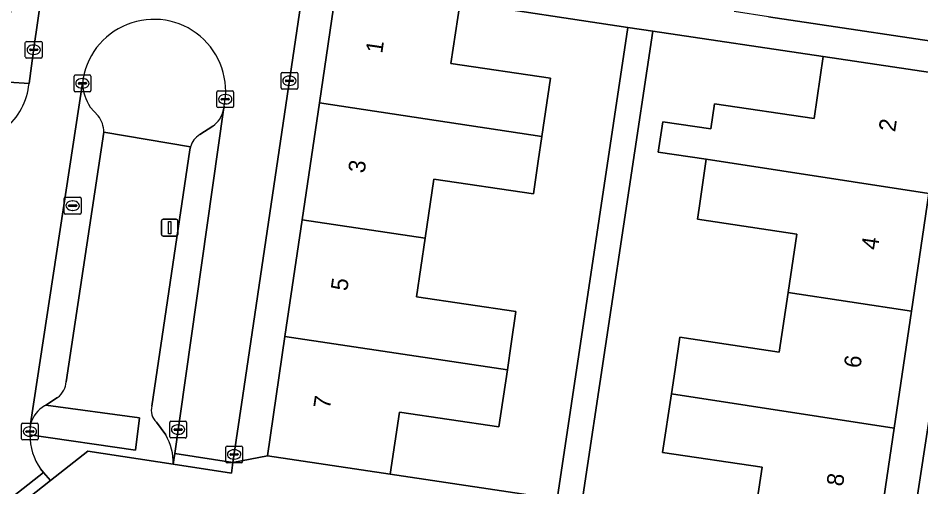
# Model space of a CAD drawing. Extents: x 163683 to 164494, y 382709 to 383872.
# Drawn here: x 163986.6 to 164040.4, y 383061.8 to 383089.7 of the extents above; entities that cross this region are included whole.
import ezdxf

# ---------------------------------------------------------------- set-up
doc = ezdxf.new("R2010")
doc.units = 0
for name, color, linetype in [('IMGEO_Erf', 7, 'Continuous'), ('IMGEO_Groenvoorziening', 7, 'Continuous'), ('IMGEO_Kolk', 7, 'Continuous'), ('IMGEO_Lichtmast', 7, 'Continuous'), ('IMGEO_Pand', 7, 'Continuous'), ('IMGEO_Pand_nummerreeks', 7, 'Continuous'), ('IMGEO_Parkeervlak_open', 7, 'Continuous'), ('IMGEO_Rijbaan_lokaal_open', 7, 'Continuous'), ('IMGEO_Rioolput', 7, 'Continuous'), ('IMGEO_Voetpad_open', 7, 'Continuous')]:
    doc.layers.add(name, color=color, linetype=linetype)

msp = doc.modelspace()

# ---------------------------------------------------------------- linework, layer by layer
at = {"layer": 'IMGEO_Erf'}
for points in [[(164022.964, 383089.182), (164012.951, 383090.682), (164012.41, 383087.025), (164018.347, 383086.148), (164017.834, 383082.676), (164017.616, 383081.202), (164017.328, 383079.253), (164011.392, 383080.13), (164010.87, 383076.601), (164010.353, 383073.107), (164016.29, 383072.23), (164016.005, 383070.301), (164015.775, 383068.743), (164015.274, 383065.354), (164009.338, 383066.231), (164008.789, 383062.521), (164018.747, 383061.027)], [(164033.045, 383076.853), (164027.111, 383077.737), (164027.209, 383078.398), (164027.643, 383081.312), (164024.777, 383081.738), (164025.045, 383083.549), (164027.913, 383083.122), (164028.136, 383084.621), (164034.07, 383083.737), (164034.621, 383087.436), (164024.449, 383088.96), (164020.223, 383060.805), (164030.426, 383059.273), (164030.971, 383062.937), (164025.038, 383063.821), (164025.558, 383067.31), (164025.775, 383068.767), (164026.062, 383070.695), (164031.996, 383069.811), (164032.527, 383073.373)]]:
    msp.add_lwpolyline(points, close=True, dxfattribs=at)
at = {"layer": 'IMGEO_Groenvoorziening'}
for points in [[(164031.356, 383089.811), (164044.132, 383087.893), (164043.843, 383085.984), (164043.851, 383085.289)], [(163990.898, 383084.429), (163991.368, 383083.909)], [(163998.849, 383084.264), (163998.879, 383084.473)], [(163996.842, 383081.879), (163996.877, 383082.051), (163991.711, 383082.931), (163989.459, 383068.037)], [(163991.711, 383082.931), (163996.877, 383082.051)], [(163997.425, 383082.781), (163998.2, 383083.289)], [(163994.577, 383066.591), (163996.842, 383081.879)], [(163988.951, 383067.097), (163988.239, 383066.641), (163993.84, 383065.897), (163993.591, 383063.961), (163987.293, 383064.864)], [(163987.293, 383064.864), (163993.591, 383063.961), (163993.84, 383065.897), (163988.239, 383066.641)], [(163988.239, 383066.641), (163988.177, 383066.601)], [(163987.342, 383065.521), (163987.311, 383065.284)], [(163995.403, 383064.865), (163994.844, 383065.639)], [(163987.926, 383062.844), (163988.107, 383062.634), (163988.526, 383062.149), (163990.75, 383063.896), (163995.848, 383063.119)]]:
    msp.add_lwpolyline(points, dxfattribs=at)
for centre, radius, start, end in [((163994.69, 383085.376), 4.285, 347.8361, 173.7169), ((163993.176, 383085.967), 2.748, 182.5462, 214.0321), ((163997.302, 383084.59), 1.581, 304.6088, 348.0925), ((163990.076, 383082.907), 1.635, 0.8498, 37.8033), ((163998.08, 383081.718), 1.249, 121.6656, 164.5444), ((163988.193, 383068.109), 1.268, 333.0123, 356.7282), ((163988.199, 383068.114), 1.265, 306.4834, 332.7039), ((163989.048, 383065.065), 1.766, 119.5576, 165.0237), ((163995.453, 383066.323), 0.916, 163.0057, 228.3279), ((163990.981, 383064.916), 3.688, 174.2788, 180.8131), ((163990.996, 383064.915), 3.704, 180.7944, 214.004), ((163992.652, 383063.234), 3.198, 357.9368, 30.6602)]:
    msp.add_arc(centre, radius, start, end, dxfattribs=at)
at = {"layer": 'IMGEO_Kolk'}
for p, q in [((163987.1, 383088.346), (163987.952, 383088.346)), ((163987.025, 383087.42), (163987.025, 383088.272)), ((163987.284, 383087.84), (163987.284, 383087.852)), ((163987.722, 383087.803), (163987.324, 383087.803)), ((163987.327, 383087.889), (163987.725, 383087.889)), ((163987.513, 383088.126), (163987.538, 383088.126)), ((163987.768, 383087.852), (163987.768, 383087.84)), ((163988.026, 383088.272), (163988.026, 383087.42)), ((163987.952, 383087.346), (163987.1, 383087.346)), ((163987.536, 383087.566), (163987.511, 383087.566)), ((163989.929, 383085.415), (163989.929, 383086.267)), ((163990.004, 383086.341), (163990.856, 383086.341)), ((163990.93, 383086.267), (163990.93, 383085.415)), ((164002.275, 383085.569), (164002.275, 383086.421)), ((164002.35, 383086.495), (164003.202, 383086.495)), ((164002.763, 383086.275), (164002.788, 383086.275)), ((164003.276, 383086.421), (164003.276, 383085.569)), ((163990.188, 383085.835), (163990.188, 383085.847)), ((163990.626, 383085.798), (163990.228, 383085.798)), ((163990.231, 383085.884), (163990.629, 383085.884)), ((163990.417, 383086.121), (163990.442, 383086.121)), ((163990.672, 383085.847), (163990.672, 383085.835)), ((164002.534, 383085.989), (164002.534, 383086.001)), ((164002.972, 383085.952), (164002.574, 383085.952)), ((164002.577, 383086.038), (164002.975, 383086.038)), ((164002.786, 383085.715), (164002.761, 383085.715)), ((164003.018, 383086.001), (164003.018, 383085.989)), ((163990.856, 383085.341), (163990.004, 383085.341)), ((163990.44, 383085.561), (163990.415, 383085.561)), ((163998.445, 383084.466), (163998.445, 383085.318)), ((163998.52, 383085.392), (163999.372, 383085.392)), ((163998.933, 383085.172), (163998.958, 383085.172)), ((163999.446, 383085.318), (163999.446, 383084.466)), ((164003.202, 383085.495), (164002.35, 383085.495)), ((163998.704, 383084.886), (163998.704, 383084.898)), ((163999.142, 383084.849), (163998.744, 383084.849)), ((163998.747, 383084.935), (163999.145, 383084.935)), ((163998.956, 383084.612), (163998.931, 383084.612)), ((163999.188, 383084.898), (163999.188, 383084.886)), ((163999.372, 383084.392), (163998.52, 383084.392)), ((163995.713, 383065.685), (163996.565, 383065.685)), ((163986.795, 383064.642), (163986.795, 383065.494)), ((163986.87, 383065.568), (163987.722, 383065.568)), ((163987.283, 383065.348), (163987.308, 383065.348)), ((163987.796, 383065.494), (163987.796, 383064.642)), ((163995.638, 383064.759), (163995.638, 383065.611)), ((163995.897, 383065.179), (163995.897, 383065.191)), ((163996.335, 383065.142), (163995.937, 383065.142)), ((163995.94, 383065.228), (163996.338, 383065.228)), ((163996.126, 383065.465), (163996.151, 383065.465)), ((163996.381, 383065.191), (163996.381, 383065.179)), ((163996.639, 383065.611), (163996.639, 383064.759)), ((163987.054, 383065.062), (163987.054, 383065.074)), ((163987.492, 383065.025), (163987.094, 383065.025)), ((163987.097, 383065.111), (163987.495, 383065.111)), ((163987.306, 383064.788), (163987.281, 383064.788)), ((163987.538, 383065.074), (163987.538, 383065.062)), ((163996.565, 383064.685), (163995.713, 383064.685)), ((163996.149, 383064.905), (163996.124, 383064.905)), ((163987.722, 383064.568), (163986.87, 383064.568)), ((163998.98, 383063.28), (163998.98, 383064.132)), ((163999.055, 383064.206), (163999.907, 383064.206)), ((163999.981, 383064.132), (163999.981, 383063.28)), ((163999.239, 383063.7), (163999.239, 383063.712)), ((163999.677, 383063.663), (163999.279, 383063.663)), ((163999.282, 383063.749), (163999.68, 383063.749)), ((163999.468, 383063.986), (163999.493, 383063.986)), ((163999.723, 383063.712), (163999.723, 383063.7)), ((163999.907, 383063.206), (163999.055, 383063.206)), ((163999.491, 383063.426), (163999.466, 383063.426))]:
    msp.add_line(p, q, dxfattribs=at)
for points in [[(163987.1, 383088.346), (163987.952, 383088.346)], [(163987.025, 383087.42), (163987.025, 383088.272)], [(163988.026, 383088.272), (163988.026, 383087.42)], [(163987.952, 383087.346), (163987.1, 383087.346)], [(163989.929, 383085.415), (163989.929, 383086.267)], [(163990.004, 383086.341), (163990.856, 383086.341)], [(163990.93, 383086.267), (163990.93, 383085.415)], [(164002.275, 383085.569), (164002.275, 383086.421)], [(164002.35, 383086.495), (164003.202, 383086.495)], [(164003.276, 383086.421), (164003.276, 383085.569)], [(163990.856, 383085.341), (163990.004, 383085.341)], [(163998.445, 383084.466), (163998.445, 383085.318)], [(163998.52, 383085.392), (163999.372, 383085.392)], [(163999.446, 383085.318), (163999.446, 383084.466)], [(164003.202, 383085.495), (164002.35, 383085.495)], [(163999.372, 383084.392), (163998.52, 383084.392)], [(163995.713, 383065.685), (163996.565, 383065.685)], [(163986.795, 383064.642), (163986.795, 383065.494)], [(163986.87, 383065.568), (163987.722, 383065.568)], [(163987.796, 383065.494), (163987.796, 383064.642)], [(163995.638, 383064.759), (163995.638, 383065.611)], [(163996.639, 383065.611), (163996.639, 383064.759)], [(163996.565, 383064.685), (163995.713, 383064.685)], [(163987.722, 383064.568), (163986.87, 383064.568)], [(163998.98, 383063.28), (163998.98, 383064.132)], [(163999.055, 383064.206), (163999.907, 383064.206)], [(163999.981, 383064.132), (163999.981, 383063.28)], [(163999.907, 383063.206), (163999.055, 383063.206)]]:
    msp.add_lwpolyline(points, dxfattribs=at)
for centre, radius, start, end in [((163987.102, 383088.27), 0.0765, 91.552, 178.448), ((163987.102, 383088.27), 0.0765, 91.552, 178.448), ((163987.95, 383088.27), 0.0765, 1.552, 88.448), ((163987.95, 383088.27), 0.0765, 1.552, 88.448), ((163987.324, 383087.849), 0.0403, 85.8775, 175.7526), ((163987.321, 383087.839), 0.0366, 178.938, 274.7102), ((163987.725, 383087.846), 0.043, 264.8664, 352.4533), ((163987.729, 383087.851), 0.0386, 1.7309, 96.639), ((163987.102, 383087.422), 0.0765, 181.552, 268.448), ((163987.102, 383087.422), 0.0765, 181.552, 268.448), ((163987.95, 383087.422), 0.0765, 271.552, 358.448), ((163987.95, 383087.422), 0.0765, 271.552, 358.448), ((163990.006, 383086.265), 0.0765, 91.552, 178.448), ((163990.006, 383086.265), 0.0765, 91.552, 178.448), ((163990.854, 383086.265), 0.0765, 1.552, 88.448), ((163990.854, 383086.265), 0.0765, 1.552, 88.448), ((164002.352, 383086.419), 0.0765, 91.552, 178.448), ((164002.352, 383086.419), 0.0765, 91.552, 178.448), ((164003.2, 383086.419), 0.0765, 1.552, 88.448), ((164003.2, 383086.419), 0.0765, 1.552, 88.448), ((163990.228, 383085.844), 0.0403, 85.8775, 175.7526), ((163990.225, 383085.834), 0.0366, 178.938, 274.7102), ((163990.629, 383085.841), 0.043, 264.8664, 352.4533), ((163990.633, 383085.846), 0.0386, 1.7309, 96.639), ((164002.574, 383085.998), 0.0403, 85.8775, 175.7526), ((164002.571, 383085.988), 0.0366, 178.938, 274.7102), ((164002.975, 383085.995), 0.043, 264.8664, 352.4533), ((164002.979, 383086), 0.0386, 1.7309, 96.639), ((163990.006, 383085.417), 0.0765, 181.552, 268.448), ((163990.006, 383085.417), 0.0765, 181.552, 268.448), ((163990.854, 383085.417), 0.0765, 271.552, 358.448), ((163990.854, 383085.417), 0.0765, 271.552, 358.448), ((163998.522, 383085.316), 0.0765, 91.552, 178.448), ((163998.522, 383085.316), 0.0765, 91.552, 178.448), ((163999.37, 383085.316), 0.0765, 1.552, 88.448), ((163999.37, 383085.316), 0.0765, 1.552, 88.448), ((164002.352, 383085.571), 0.0765, 181.552, 268.448), ((164002.352, 383085.571), 0.0765, 181.552, 268.448), ((164003.2, 383085.571), 0.0765, 271.552, 358.448), ((164003.2, 383085.571), 0.0765, 271.552, 358.448), ((163998.744, 383084.895), 0.0403, 85.8775, 175.7526), ((163998.741, 383084.885), 0.0366, 178.938, 274.7102), ((163999.145, 383084.892), 0.043, 264.8664, 352.4533), ((163999.149, 383084.897), 0.0386, 1.7309, 96.639), ((163998.522, 383084.468), 0.0765, 181.552, 268.448), ((163998.522, 383084.468), 0.0765, 181.552, 268.448), ((163999.37, 383084.468), 0.0765, 271.552, 358.448), ((163999.37, 383084.468), 0.0765, 271.552, 358.448), ((163995.715, 383065.609), 0.0765, 91.552, 178.448), ((163995.715, 383065.609), 0.0765, 91.552, 178.448), ((163996.563, 383065.609), 0.0765, 1.552, 88.448), ((163996.563, 383065.609), 0.0765, 1.552, 88.448), ((163986.872, 383065.492), 0.0765, 91.552, 178.448), ((163986.872, 383065.492), 0.0765, 91.552, 178.448), ((163987.72, 383065.492), 0.0765, 1.552, 88.448), ((163987.72, 383065.492), 0.0765, 1.552, 88.448), ((163995.937, 383065.188), 0.0403, 85.8775, 175.7526), ((163995.934, 383065.178), 0.0366, 178.938, 274.7102), ((163996.338, 383065.185), 0.043, 264.8664, 352.4533), ((163996.342, 383065.19), 0.0386, 1.7309, 96.639), ((163986.872, 383064.644), 0.0765, 181.552, 268.448), ((163986.872, 383064.644), 0.0765, 181.552, 268.448), ((163987.094, 383065.071), 0.0403, 85.8775, 175.7526), ((163987.091, 383065.061), 0.0366, 178.938, 274.7102), ((163987.495, 383065.068), 0.043, 264.8664, 352.4533), ((163987.499, 383065.073), 0.0386, 1.7309, 96.639), ((163987.72, 383064.644), 0.0765, 271.552, 358.448), ((163987.72, 383064.644), 0.0765, 271.552, 358.448), ((163995.715, 383064.761), 0.0765, 181.552, 268.448), ((163995.715, 383064.761), 0.0765, 181.552, 268.448), ((163996.563, 383064.761), 0.0765, 271.552, 358.448), ((163996.563, 383064.761), 0.0765, 271.552, 358.448), ((163999.057, 383064.13), 0.0765, 91.552, 178.448), ((163999.057, 383064.13), 0.0765, 91.552, 178.448), ((163999.905, 383064.13), 0.0765, 1.552, 88.448), ((163999.905, 383064.13), 0.0765, 1.552, 88.448), ((163999.279, 383063.709), 0.0403, 85.8775, 175.7526), ((163999.276, 383063.699), 0.0366, 178.938, 274.7102), ((163999.68, 383063.706), 0.043, 264.8664, 352.4533), ((163999.684, 383063.711), 0.0386, 1.7309, 96.639), ((163999.057, 383063.282), 0.0765, 181.552, 268.448), ((163999.057, 383063.282), 0.0765, 181.552, 268.448), ((163999.905, 383063.282), 0.0765, 271.552, 358.448), ((163999.905, 383063.282), 0.0765, 271.552, 358.448)]:
    msp.add_arc(centre, radius, start, end, dxfattribs=at)
for centre, major_axis, ratio, start_param, end_param in [((163987.512, 383087.846), (-0.387, 0.002), 0.722429, 4.712389, 7.853982), ((163987.537, 383087.846), (-0.39, 0.002), 0.717154, 1.570796, 4.712389), ((164002.762, 383085.995), (-0.387, 0.002), 0.722429, 4.712389, 7.853982), ((164002.787, 383085.995), (-0.39, 0.002), 0.717154, 1.570796, 4.712389), ((163990.416, 383085.841), (-0.387, 0.002), 0.722429, 4.712389, 7.853982), ((163990.441, 383085.841), (-0.39, 0.002), 0.717154, 1.570796, 4.712389), ((163998.932, 383084.892), (-0.387, 0.002), 0.722429, 4.712389, 7.853982), ((163998.957, 383084.892), (-0.39, 0.002), 0.717154, 1.570796, 4.712389), ((163987.282, 383065.068), (-0.387, 0.002), 0.722429, 4.712389, 7.853982), ((163987.307, 383065.068), (-0.39, 0.002), 0.717154, 1.570796, 4.712389), ((163996.125, 383065.185), (-0.387, 0.002), 0.722429, 4.712389, 7.853982), ((163996.15, 383065.185), (-0.39, 0.002), 0.717154, 1.570796, 4.712389), ((163999.467, 383063.706), (-0.387, 0.002), 0.722429, 4.712389, 7.853982), ((163999.492, 383063.706), (-0.39, 0.002), 0.717154, 1.570796, 4.712389)]:
    msp.add_ellipse(centre, major_axis=major_axis, ratio=ratio, start_param=start_param, end_param=end_param, dxfattribs=at)
at = {"layer": 'IMGEO_Lichtmast'}
for p, q in [((163995.139, 383076.834), (163995.139, 383077.634)), ((163995.139, 383077.634), (163995.139, 383076.834)), ((163995.239, 383077.734), (163996.029, 383077.734)), ((163996.029, 383077.734), (163995.239, 383077.734)), ((163996.129, 383077.634), (163996.129, 383076.834)), ((163996.129, 383076.834), (163996.129, 383077.634)), ((163996.029, 383076.734), (163995.239, 383076.734)), ((163995.239, 383076.734), (163996.029, 383076.734))]:
    msp.add_line(p, q, dxfattribs=at)
msp.add_lwpolyline([(163995.559, 383077.609), (163995.709, 383077.609), (163995.709, 383076.859), (163995.559, 383076.859), (163995.559, 383077.609)], dxfattribs=at)
for centre, start, end in [((163995.239, 383077.634), 90, 180), ((163995.239, 383077.634), 90, 180), ((163996.029, 383077.634), 0, 90), ((163996.029, 383077.634), 360, 90), ((163995.239, 383076.834), 180, 270), ((163995.239, 383076.834), 180, 270), ((163996.029, 383076.834), 270, 0), ((163996.029, 383076.834), 270, 0)]:
    msp.add_arc(centre, 0.1, start, end, dxfattribs=at)
at = {"layer": 'IMGEO_Pand'}
for points in [[(164004.564, 383084.669), (164017.834, 383082.676), (164018.347, 383086.148), (164012.41, 383087.025), (164012.951, 383090.682), (164005.606, 383091.746)], [(164041.955, 383086.344), (164034.621, 383087.436), (164034.07, 383083.737), (164028.136, 383084.621), (164027.913, 383083.122), (164025.045, 383083.549), (164024.777, 383081.738), (164027.643, 383081.312), (164040.913, 383079.27)], [(164003.538, 383077.702), (164010.87, 383076.601), (164011.392, 383080.13), (164017.328, 383079.253), (164017.616, 383081.202), (164017.834, 383082.676), (164004.564, 383084.669)], [(164040.913, 383079.27), (164027.643, 383081.312), (164027.209, 383078.398), (164027.111, 383077.737), (164033.045, 383076.853), (164032.527, 383073.373), (164039.878, 383072.242)], [(164015.775, 383068.743), (164016.005, 383070.301), (164016.29, 383072.23), (164010.353, 383073.107), (164010.87, 383076.601), (164003.538, 383077.702), (164002.512, 383070.735)], [(164032.527, 383073.373), (164031.996, 383069.811), (164026.062, 383070.695), (164025.775, 383068.767), (164025.558, 383067.31), (164038.851, 383065.265), (164039.878, 383072.242)], [(164015.775, 383068.743), (164002.512, 383070.735), (164001.464, 383063.621), (164008.789, 383062.521), (164009.338, 383066.231), (164015.274, 383065.354)], [(164025.558, 383067.31), (164025.038, 383063.821), (164030.971, 383062.937), (164030.426, 383059.273), (164037.802, 383058.142), (164038.851, 383065.265)]]:
    msp.add_lwpolyline(points, close=True, dxfattribs=at)
at = {"layer": 'IMGEO_Parkeervlak_open'}
for points in [[(163990.43, 383085.845), (163987.342, 383065.521)], [(163991.368, 383083.909), (163990.898, 383084.429)], [(163995.848, 383063.119), (163995.938, 383063.753), (163998.849, 383084.264)], [(163989.459, 383068.037), (163991.711, 383082.931)], [(163998.2, 383083.289), (163997.425, 383082.781)], [(163996.877, 383082.051), (163996.842, 383081.879), (163994.577, 383066.591)], [(163988.177, 383066.601), (163988.239, 383066.641), (163988.951, 383067.097)], [(163994.844, 383065.639), (163995.403, 383064.865)]]:
    msp.add_lwpolyline(points, dxfattribs=at)
for centre, radius, start, end in [((163993.176, 383085.967), 2.748, 182.5462, 214.0321), ((163997.302, 383084.59), 1.581, 304.6088, 348.0925), ((163990.076, 383082.907), 1.635, 0.8498, 37.8033), ((163998.08, 383081.718), 1.249, 121.6656, 164.5444), ((163988.193, 383068.109), 1.268, 333.0123, 356.7282), ((163988.199, 383068.114), 1.265, 306.4834, 332.7039), ((163989.048, 383065.065), 1.766, 119.5576, 165.0237), ((163995.453, 383066.323), 0.916, 163.0057, 228.3279), ((163992.652, 383063.234), 3.198, 357.9368, 30.6602)]:
    msp.add_arc(centre, radius, start, end, dxfattribs=at)
at = {"layer": 'IMGEO_Rijbaan_lokaal_open'}
for points in [[(163988.304, 383093.335), (163988.28, 383093.184), (163987.541, 383087.945), (163987.247, 383085.842)], [(163998.879, 383084.473), (163998.849, 383084.264), (163995.938, 383063.753), (163999.41, 383063.224), (164000, 383067.22), (164003.533, 383091.132)], [(163987.311, 383065.284), (163987.342, 383065.521), (163990.43, 383085.845)], [(164043.851, 383085.289), (164043.854, 383085.06), (164043.271, 383081.092), (164039.653, 383057.519), (164042.978, 383056.96), (164045.921, 383076.806), (164045.976, 383077.163), (164046.054, 383077.691)], [(163984.751, 383060.838), (163985.116, 383060.277), (163988.107, 383062.634), (163987.926, 383062.844)]]:
    msp.add_lwpolyline(points, dxfattribs=at)
for points in [[(163999.41, 383063.224), (163995.938, 383063.753), (163995.848, 383063.119), (163999.316, 383062.59)], [(163985.116, 383060.277), (163985.466, 383059.738), (163988.526, 383062.149), (163988.107, 383062.634)]]:
    msp.add_lwpolyline(points, close=True, dxfattribs=at)
for centre, radius, start, end in [((163994.69, 383085.376), 4.285, 347.8361, 173.7169), ((163983.273, 383086.213), 3.991, 309.0933, 354.6592), ((163990.981, 383064.916), 3.688, 174.2788, 180.8131), ((163990.996, 383064.915), 3.704, 180.7944, 214.004)]:
    msp.add_arc(centre, radius, start, end, dxfattribs=at)
at = {"layer": 'IMGEO_Rioolput'}
for p, q in [((163989.347, 383078.118), (163989.347, 383078.97)), ((163989.422, 383079.044), (163990.274, 383079.044)), ((163989.835, 383078.824), (163989.86, 383078.824)), ((163990.348, 383078.97), (163990.348, 383078.118)), ((163989.606, 383078.538), (163989.606, 383078.55)), ((163990.044, 383078.501), (163989.646, 383078.501)), ((163989.649, 383078.587), (163990.047, 383078.587)), ((163989.858, 383078.264), (163989.833, 383078.264)), ((163990.09, 383078.55), (163990.09, 383078.538)), ((163990.274, 383078.044), (163989.422, 383078.044))]:
    msp.add_line(p, q, dxfattribs=at)
for points in [[(163989.347, 383078.118), (163989.347, 383078.97)], [(163989.422, 383079.044), (163990.274, 383079.044)], [(163990.348, 383078.97), (163990.348, 383078.118)], [(163990.274, 383078.044), (163989.422, 383078.044)]]:
    msp.add_lwpolyline(points, dxfattribs=at)
for centre, radius, start, end in [((163989.424, 383078.968), 0.0765, 91.552, 178.448), ((163989.424, 383078.968), 0.0765, 91.552, 178.448), ((163990.272, 383078.968), 0.0765, 1.552, 88.448), ((163990.272, 383078.968), 0.0765, 1.552, 88.448), ((163989.424, 383078.12), 0.0765, 181.552, 268.448), ((163989.424, 383078.12), 0.0765, 181.552, 268.448), ((163989.646, 383078.547), 0.0403, 85.8775, 175.7526), ((163989.643, 383078.537), 0.0366, 178.938, 274.7102), ((163990.047, 383078.544), 0.043, 264.8664, 352.4533), ((163990.051, 383078.549), 0.0386, 1.7309, 96.639), ((163990.272, 383078.12), 0.0765, 271.552, 358.448), ((163990.272, 383078.12), 0.0765, 271.552, 358.448)]:
    msp.add_arc(centre, radius, start, end, dxfattribs=at)
for centre, major_axis, ratio, start_param, end_param in [((163989.834, 383078.544), (-0.387, 0.002), 0.722429, 4.712389, 7.853982), ((163989.859, 383078.544), (-0.39, 0.002), 0.717154, 1.570796, 4.712389)]:
    msp.add_ellipse(centre, major_axis=major_axis, ratio=ratio, start_param=start_param, end_param=end_param, dxfattribs=at)
at = {"layer": 'IMGEO_Voetpad_open'}
for points in [[(163978.464, 383123.365), (163980.235, 383121.415), (163981.417, 383120.114), (163983.586, 383117.726), (163989.035, 383116.926), (163990.07, 383116.819), (163985.838, 383088.085), (163983.586, 383086.072), (163987.247, 383085.842), (163987.541, 383087.945), (163988.28, 383093.184), (163988.304, 383093.335), (163988.055, 383093.357), (163989.902, 383106.278), (163990.663, 383111.596), (163991.352, 383116.509), (163991.634, 383118.52), (163990.354, 383118.89), (163984.672, 383119.707), (163984.546, 383119.848), (163980.732, 383124.09)], [(163987.247, 383085.842), (163983.586, 383086.072), (163934.941, 383093.086)], [(164003.455, 383092.05), (164005.606, 383091.746), (164012.951, 383090.682), (164022.964, 383089.182), (164024.449, 383088.96), (164034.621, 383087.436), (164041.955, 383086.344), (164043.843, 383085.984), (164044.132, 383087.893), (164031.356, 383089.811), (164029.301, 383090.12)], [(164004.564, 383084.669), (164005.606, 383091.746), (164003.455, 383092.05)], [(164003.533, 383091.132), (164000, 383067.22), (163999.41, 383063.224), (164001.464, 383063.621), (164002.512, 383070.735), (164003.538, 383077.702), (164004.564, 383084.669)], [(164056.633, 383055.356), (164054.596, 383055.242), (164054.5, 383054.599), (164051.188, 383055.135), (164042.84, 383056.324), (164039.556, 383056.876), (164039.653, 383057.519), (164037.802, 383058.142), (164030.426, 383059.273), (164020.223, 383060.805), (164018.747, 383061.027), (164008.789, 383062.521), (164001.464, 383063.621), (163999.41, 383063.224), (163999.316, 383062.59), (163995.848, 383063.119), (163990.75, 383063.896), (163988.526, 383062.149), (163985.466, 383059.738)]]:
    msp.add_lwpolyline(points, dxfattribs=at)
for points in [[(164024.449, 383088.96), (164022.964, 383089.182), (164018.747, 383061.027), (164020.223, 383060.805)], [(164043.271, 383081.092), (164043.854, 383085.06), (164043.851, 383085.289), (164043.843, 383085.984), (164041.955, 383086.344), (164040.913, 383079.27), (164039.878, 383072.242), (164038.851, 383065.265), (164037.802, 383058.142), (164039.653, 383057.519)]]:
    msp.add_lwpolyline(points, close=True, dxfattribs=at)
msp.add_arc((163983.273, 383086.213), 3.991, 309.0933, 354.6592, dxfattribs=at)

# ---------------------------------------------------------------- texts
at = {"layer": 'IMGEO_Pand_nummerreeks'}
for s, rotation, p in [('1', 81.6222, (164008.31, 383087.593)), ('2', 81.6236, (164038.902, 383082.911)), ('3', 81.6222, (164007.258, 383080.449)), ('4', 81.6236, (164037.864, 383075.863)), ('5', 81.6222, (164006.222, 383073.417)), ('6', 81.6229, (164036.826, 383068.812)), ('7', 81.6222, (164005.187, 383066.386)), ('8', 81.6229, (164035.789, 383061.766))]:
    msp.add_text(s, height=1, rotation=rotation, dxfattribs=at).set_placement(p)

doc.saveas('drawing.dxf')
